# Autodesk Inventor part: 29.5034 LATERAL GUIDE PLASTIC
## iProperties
Created: 2007-05
Part Number: 29.5034 LATERAL GUIDE PLASTIC
Material: UHMW, White
Document SubType Name: Modeling
Designer: Andy Moles
Author: Andy Moles
